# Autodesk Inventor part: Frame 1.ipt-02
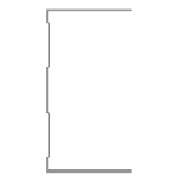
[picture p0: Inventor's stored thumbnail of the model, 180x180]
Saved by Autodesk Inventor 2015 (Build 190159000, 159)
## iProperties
IsCustomPart: 1
Created: 2015-04
Part Number: Frame 1.ipt-02
Material: Aluminum 6061
Description: Kévin Novo
Document SubType Name: Modeling
Standard: Kevin
Designer: suporte
Standards Organization: Kevin
Language: en-US
Size Designation: (Unnamed 2)
Categories: <MemberInstance><Categories><Category DisplayName="Structural Shapes" InternalName="089c4875-fa83-4c05-b084-43b9cc11f5ed" Mnemonic="GRDR"><CategoryParameter Dis
Density: 2.7 g/cm^3
Appearance: Aluminum - Flat
_CCFamilyMember: 2
_CCFamilyDisplayName: Kévin - Kévin Novo
_FrameMemberDoc: Frame Member File
_Version: 15.0.0
_GetPNFromCC: 1
G_W: 50,000 mm
G_H: 75,000 mm
G_L: 2100,000 mm
+501D1CD4-C566-4F31-A21D-ABCD7C629FFC+CUTDETAIL1: Notch
+4815FBBF-8F18-4682-805C-1E3F3A73840C+CUTDETAIL2: Notch
Author: suporte
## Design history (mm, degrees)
node "Start Plane"
node "End Plane"
sketch "Sketch"
  geometry: L1 (24.7, 37.5)-(24.7, 36.9); L2 (24.7, 36.9)-(-24.7, 36.9); L3 (-24.7, -36.9)-(24.7, -36.9); L4 (24.7, -36.9)-(24.7, -37.5); L5 (24.7, -37.5)-(-25.3, -37.5); L6 (-25.3, 37.5)-(24.7, 37.5); L7 (-24.7, 36.9)-(-24.7, 31.9); L8 (-24.7, 31.9)-(-23.3, 30.5); L9 (-23.3, 30.5)-(-23.3, 10.934); L10 (-23.3, 10.934)-(-24.7, 9.534); L11 (-24.7, 9.534)-(-24.7, -9.534); L12 (-24.7, -9.534)-(-23.3, -10.934); L13 (-23.3, -10.934)-(-23.3, -30.5); L14 (-23.3, -30.5)-(-24.7, -31.9); L15 (-24.7, -31.9)-(-24.7, -36.9); L16 (-25.3, -37.5)-(-25.3, -31.651); L17 (-25.3, -31.651)-(-23.9, -30.251); L18 (-23.9, -30.251)-(-23.9, -11.183); L19 (-23.9, -11.183)-(-25.3, -9.783); L20 (-25.3, -9.783)-(-25.3, 9.783); L21 (-25.3, 9.783)-(-23.9, 11.183); L22 (-23.9, 11.183)-(-23.9, 30.251); L23 (-23.9, 30.251)-(-25.3, 31.651); L24 (-25.3, 31.651)-(-25.3, 37.5); L25 (-25.3, 0)-(30.37, 0); 3 further points
  constraints: 50 end point, 10 point on line, 9 parallel, 5 perpendicular, 4 equal length, 3 midpoint, 3 vertical, 2 vertical alignment, 1 collinear, 1 horizontal, 1 horizontal alignment
  dimensions: "d3" = 0.6 distance of L1.start L1.end (= d6); "d5" = 75 distance between parallel lines of L5 L6; "d6" = 0.6 distance between parallel lines of L24 L7 (= d8); "d7" = 0.6 distance between parallel lines of L8 L23 (= d8); "d8" = 0.6 distance between parallel lines of L22 L9 (= d12); "Espessura" = 0.6 distance between parallel lines of L17 L14; "d10" = 0.6 distance between parallel lines of L13 L18 (= Espessura); "d11" = 0.6 distance between parallel lines of L12 L19 (= Espessura); "d12" = 0.6 distance between parallel lines of L21 L10 (= d11); "d13" = 5 distance of L2.end L7.end; "d15" = 135 deg angle of L9 L8; "d16" = 2 distance between parallel lines of L24 L9; "d17" = 50 distance of L6.start L1.start
extrude "Body" join sketch "Sketch" stored distance "d24" = 0.13; taper "d25" = 0 deg
node "Driven Length"
  sketch "Sketch10"
    geometry: L1 (0, 0)-(10, 0) reference
    constraints: 2 end point, 1 horizontal
  workplane "Work Plane7"
  sketch "Sketch11"
    geometry: L1 (-2, 0)-(12, 0) reference; L2 (-2, 2100)-(12, 2100) reference
    dimensions: "d27" = 2100 distance between parallel lines of L1 L2 (derived)
workplane "Work Plane8"
workplane "Work Plane9"
workplane "Work Plane10"
sketch "Sketch12"
  geometry: L1 (24.7, 37.5)-(24.7, 36.9); L2 (24.7, 36.9)-(-24.7, 36.9); L3 (-24.7, 36.9)-(-24.7, 31.9); L4 (-24.7, 31.9)-(-23.3, 30.5); L5 (-23.3, 30.5)-(-23.3, 10.934); L6 (-23.3, 10.934)-(-24.7, 9.534); L7 (-24.7, 9.534)-(-24.7, -9.534); L8 (-24.7, -9.534)-(-23.3, -10.934); L9 (-23.3, -10.934)-(-23.3, -30.5); L10 (-23.3, -30.5)-(-24.7, -31.9); L11 (-24.7, -31.9)-(-24.7, -36.9); L12 (-24.7, -36.9)-(24.7, -36.9); L13 (24.7, -36.9)-(24.7, -37.5); L14 (24.7, -37.5)-(-25.3, -37.5); L15 (-25.3, -37.5)-(-25.3, -31.651); L16 (-25.3, -31.651)-(-23.9, -30.251); L17 (-23.9, -30.251)-(-23.9, -11.183); L18 (-23.9, -11.183)-(-25.3, -9.783); L19 (-25.3, -9.783)-(-25.3, 9.783); L20 (-25.3, 9.783)-(-23.9, 11.183); L21 (-23.9, 11.183)-(-23.9, 30.251); L22 (-23.9, 30.251)-(-25.3, 31.651); L23 (-25.3, 31.651)-(-25.3, 37.5); L24 (-25.3, 37.5)-(24.7, 37.5)
  constraints: 48 end point, 10 point on line
extrude "Extrusion3" cut sketch "Sketch12" stored distance "d36" = 0.13; taper "d37" = 0 deg
workplane "Work Plane11"
workplane "Work Plane12"
workplane "Work Plane13"
sketch "Sketch13"
  geometry: L1 (24.7, 37.5)-(24.7, 36.9); L2 (24.7, 36.9)-(-24.7, 36.9); L3 (-24.7, 36.9)-(-24.7, 31.9); L4 (-24.7, 31.9)-(-23.3, 30.5); L5 (-23.3, 30.5)-(-23.3, 10.934); L6 (-23.3, 10.934)-(-24.7, 9.534); L7 (-24.7, 9.534)-(-24.7, -9.534); L8 (-24.7, -9.534)-(-23.3, -10.934); L9 (-23.3, -10.934)-(-23.3, -30.5); L10 (-23.3, -30.5)-(-24.7, -31.9); L11 (-24.7, -31.9)-(-24.7, -36.9); L12 (-24.7, -36.9)-(24.7, -36.9); L13 (24.7, -36.9)-(24.7, -37.5); L14 (24.7, -37.5)-(-25.3, -37.5); L15 (-25.3, -37.5)-(-25.3, -31.651); L16 (-25.3, -31.651)-(-23.9, -30.251); L17 (-23.9, -30.251)-(-23.9, -11.183); L18 (-23.9, -11.183)-(-25.3, -9.783); L19 (-25.3, -9.783)-(-25.3, 9.783); L20 (-25.3, 9.783)-(-23.9, 11.183); L21 (-23.9, 11.183)-(-23.9, 30.251); L22 (-23.9, 30.251)-(-25.3, 31.651); L23 (-25.3, 31.651)-(-25.3, 37.5); L24 (-25.3, 37.5)-(24.7, 37.5)
  constraints: 48 end point, 10 point on line
extrude "Extrusion4" cut sketch "Sketch13" stored distance "d38" = 0.13; taper "d39" = 0 deg
body "Solid1"
other parameters: "G_OFFSET_START" = 0 [user parameter; used in 1 equation term], "G_OFFSET_END" = 0 [user parameter; used in 1 equation term], "d22" = 0 (computed from G_OFFSET_START), "G_L" = 2100 (= d27) [user parameter], "d34" = 90 deg
